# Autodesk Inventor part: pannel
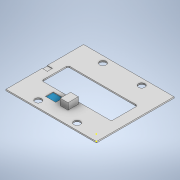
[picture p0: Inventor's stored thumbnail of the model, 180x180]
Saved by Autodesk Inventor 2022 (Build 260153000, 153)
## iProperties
Created: 2021-06
Part Number: pannel
Material: Generic
Document SubType Name: Modeling
Designer: 91876
Density: 1 g/cm^3
Appearance: Default
Author: 91876
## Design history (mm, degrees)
sketch "Sketch17"
  geometry: L1 (0, 0)-(700, 0); L2 (700, 0)-(700, -600); L3 (700, -600)-(0, -600); L4 (0, -600)-(0, 0)
  constraints: 8 end point, 2 parallel, 1 horizontal, 1 perpendicular
  dimensions: "d51" = 700 distance of L2.end L3.end; "d52" = 600 distance of L1.end L2.end
extrude "Extrusion10" new body sketch "Sketch17" distance "d53" = 10; taper "d54" = 0 deg
sketch "Sketch18"
  geometry: L1 (-620, 195)-(-80, 195); L2 (-80, 195)-(-80, 400); L3 (-80, 400)-(-620, 400); L4 (-620, 400)-(-620, 195); L5 (-700, 0)-(0, 0) reference; L6 (0, 0)-(0, 600) reference
  constraints: 8 end point, 2 parallel, 1 horizontal, 1 perpendicular
  dimensions: "d55" = 540 distance of L3.end L2.end; "d56" = 205 distance of L2.end L1.end; "d57" = 195 distance between parallel lines of L5 L1; "d58" = 80 distance between parallel lines of L6 L2
extrude "Extrusion11" cut sketch "Sketch18" extent not by distance; stored distance "d59" = 0; taper "d60" = 0 deg
sketch "Sketch19"
  geometry: L1 (-380, 100)-(-320, 100); L2 (-320, 100)-(-320, 180); L3 (-320, 180)-(-380, 180); L4 (-380, 180)-(-380, 100); L5 (-700, 600)-(-700, 0) reference; L6 (-80, 195)-(-620, 195) reference; 1 further point
  constraints: 8 end point, 2 parallel, 1 horizontal, 1 perpendicular
  dimensions: "d61" = 60 distance of L3.end L2.end; "d62" = 80 distance of L2.end L1.end; "d63" = 320 distance between parallel lines of L5 L4; "d115" = 15 distance between parallel lines of L6 L3
extrude "Extrusion12" join sketch "Sketch19" distance "d64" = 50; taper "d65" = 0 deg
fillet "Fillet5" dims "d66" = 15
fillet "Fillet6" dims "d67" = 15
fillet "Fillet7" dims "d68" = 15
fillet "Fillet8" dims "d69" = 15
sketch "Sketch25"
  geometry: L1 (0, 0)-(0, 600) reference; L2 (-700, 0)-(0, 0) reference; C1 r 25 at (-200, 50)
  constraints: 1 centre point
  dimensions: "d92" = 50 diameter of C1; "d93" = 200 distance from line of L1 C1.centre; "d94" = 50 distance from line of L2 C1.centre
extrude "Extrusion17" cut sketch "Sketch25" extent not by distance; stored distance "d95" = 0; taper "d96" = 0 deg
sketch "Sketch26"
  geometry: L1 (-700, 0)-(0, 0) reference; L2 (-700, 600)-(-700, 0) reference; C1 r 25 at (-500, 50)
  constraints: 1 centre point
  dimensions: "d97" = 50 diameter of C1; "d98" = 50 distance from line of L1 C1.centre; "d99" = 200 distance from line of L2 C1.centre
extrude "Extrusion18" cut sketch "Sketch26" extent not by distance; stored distance "d100" = 0; taper "d101" = 0 deg
sketch "Sketch28"
  geometry: L1 (0, 600)-(-700, 600) reference; L2 (0, 0)-(0, 600) reference; L3 (-700, 600)-(-700, 0) reference; C1 r 25 at (-200, 550); C2 r 25 at (-500, 550)
  constraints: 2 centre point
  dimensions: "d102" = 50 diameter of C1; "d103" = 50 diameter of C2; "d104" = 50 distance from line of L1 C1.centre; "d105" = 200 distance from line of L2 C1.centre; "d106" = 200 distance from line of L3 C2.centre; "d107" = 50 distance from line of L1 C2.centre
extrude "Extrusion19" cut sketch "Sketch28" extent not by distance; stored distance "d108" = 0; taper "d109" = 0 deg
sketch "Sketch29"
  geometry: L1 (-700, 600)-(-700, 0) reference; L2 (0, 600)-(-700, 600) reference; C1 r 25 at (-500, 550); 1 further point
  constraints: 1 centre point
  dimensions: "d110" = 50 diameter of C1; "d111" = 200 distance from line of L1 C1.centre; "d112" = 50 distance from line of L2 C1.centre
extrude "Extrusion20" cut sketch "Sketch29" extent not by distance; stored distance "d113" = 0; taper "d114" = 0 deg
sketch "Sketch31"
  geometry: 1 further point
sketch "Sketch33"
  geometry: L1 (-420, 165)-(-500, 165); L2 (-500, 165)-(-500, 105); L3 (-500, 105)-(-420, 105); L4 (-420, 105)-(-420, 165); L5 (-420, 165)-(-500, 105); L6 (-500, 165)-(-420, 105); L7 (-95, 195)-(-605, 195) reference; L8 (-700, 600)-(-700, 0) reference; 2 further points
  constraints: 12 end point, 2 midpoint, 2 parallel, 1 horizontal, 1 perpendicular
  dimensions: "d130" = 80 distance of L3.end L2.end; "d131" = 60 distance of L2.end L1.end; "d132" = 30 distance between parallel lines of L7 L1; "d133" = 200 distance between parallel lines of L8 L2
extrude "Extrusion21" cut sketch "Sketch33" distance "d134" = 5; taper "d135" = 0 deg
sketch "Sketch34"
  geometry: L1 (-660, 280)-(-700, 280); L2 (-700, 280)-(-700, 320); L3 (-700, 320)-(-660, 320); L4 (-660, 320)-(-660, 280); L5 (-660, 280)-(-700, 320); L6 (-700, 280)-(-660, 320); L7 (-700, 600)-(-700, 0) reference; L8 (0, 600)-(-700, 600) reference; 2 further points
  constraints: 12 end point, 2 midpoint, 2 parallel, 1 horizontal, 1 perpendicular
  dimensions: "d136" = 40 distance of L2.end L3.end; "d137" = 40 distance of L1.end L2.end; "d138" = 0 distance between parallel lines of L7 L2; "d139" = 280 distance between parallel lines of L8 L3
extrude "Extrusion22" cut sketch "Sketch34" distance "d140" = 5; taper "d141" = 0 deg
sketch "Sketch35"
  geometry: 1 further point
sketch "Sketch36"
  geometry: L1 (-420.259, 164.994)-(-500.259, 164.994); L2 (-500.259, 164.994)-(-500.259, 104.994); L3 (-500.259, 104.994)-(-420.259, 104.994); L4 (-420.259, 104.994)-(-420.259, 164.994); 1 further point
  constraints: 8 end point, 2 parallel, 1 horizontal, 1 perpendicular
  dimensions: "d142" = 80 distance of L3.end L2.end; "d143" = 60 distance of L2.end L1.end
split "Split1" sketch "Sketch36"
body "Solid2"
